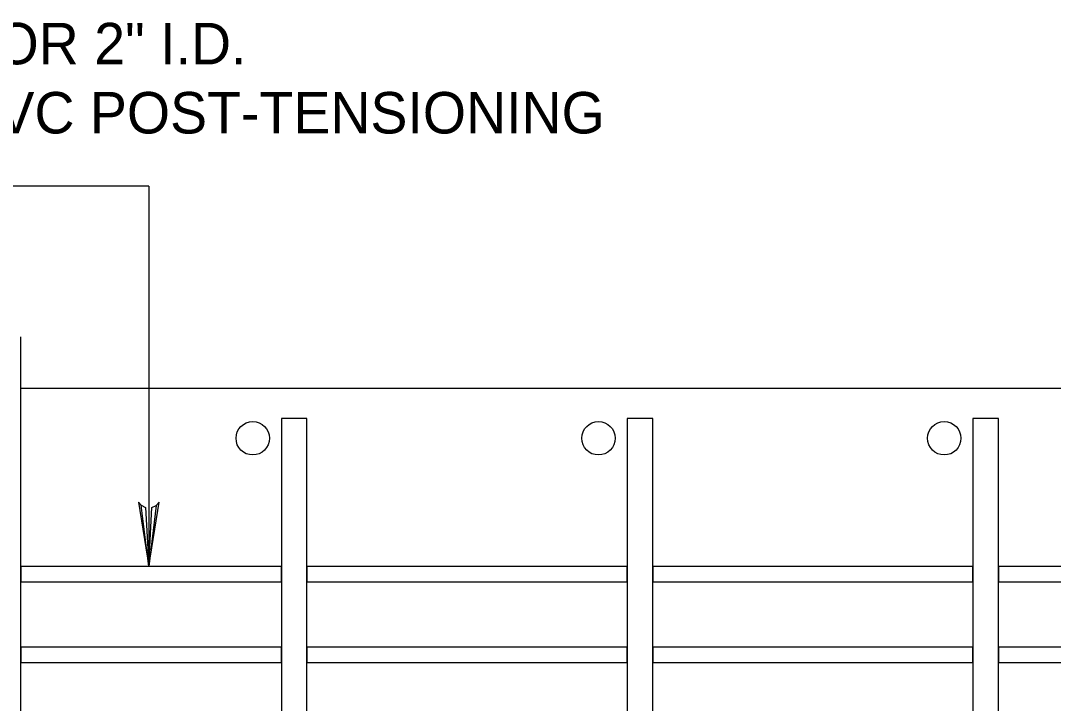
# Model space of a CAD drawing. Extents: x 641328 to 643024, y 298283 to 300065.
# Drawn here: x 642584.3 to 642658.9, y 299717.9 to 299767.3 of the extents above; entities that cross this region are included whole.
import ezdxf

# ---------------------------------------------------------------- set-up
doc = ezdxf.new("R2010")
doc.units = 0
doc.layers.add('2', color=7, linetype='Continuous')
doc.layers.add('63', color=7, linetype='Continuous')

msp = doc.modelspace()

# ---------------------------------------------------------------- linework, layer by layer
at = {"layer": '2'}
for p, q in [((642593.54, 299755.271), (642576.092, 299755.271)), ((642584.298, 299686.504), (642584.298, 299744.382)), ((642687.271, 299740.639), (642584.298, 299740.639)), ((642604.973, 299738.468), (642603.123, 299738.468)), ((642603.123, 299738.468), (642603.123, 299680.655)), ((642604.973, 299680.655), (642604.973, 299738.468)), ((642629.973, 299738.468), (642628.123, 299738.468)), ((642628.123, 299738.468), (642628.123, 299680.655)), ((642629.973, 299680.655), (642629.973, 299738.468)), ((642654.973, 299738.468), (642653.123, 299738.468)), ((642653.123, 299738.468), (642653.123, 299680.655)), ((642654.973, 299680.655), (642654.973, 299738.468))]:
    msp.add_line(p, q, dxfattribs=at)
for points in [[(642603.123, 299727.775), (642584.298, 299727.775), (642584.298, 299726.664), (642603.123, 299726.664)], [(642628.123, 299727.775), (642604.973, 299727.775), (642604.973, 299726.664), (642628.123, 299726.664)], [(642653.123, 299727.775), (642629.973, 299727.775), (642629.973, 299726.664), (642653.123, 299726.664)], [(642674.273, 299727.775), (642654.973, 299727.775), (642654.973, 299726.664), (642674.273, 299726.664)], [(642603.123, 299721.94), (642584.298, 299721.94), (642584.298, 299720.829), (642603.123, 299720.829)], [(642628.123, 299721.94), (642604.973, 299721.94), (642604.973, 299720.829), (642628.123, 299720.829)], [(642653.123, 299721.94), (642629.973, 299721.94), (642629.973, 299720.829), (642653.123, 299720.829)], [(642674.273, 299721.94), (642654.973, 299721.94), (642654.973, 299720.829), (642674.273, 299720.829)]]:
    msp.add_lwpolyline(points, close=True, dxfattribs=at)
for centre in [(642601.052, 299737.047), (642626.052, 299737.047), (642651.052, 299737.047)]:
    msp.add_circle(centre, 1.207, dxfattribs=at)
at = {"layer": '63'}
msp.add_line((642593.54, 299755.271), (642593.54, 299727.775), dxfattribs=at)
msp.add_lwpolyline([(642592.984, 299732.204), (642593.305, 299732.039), (642593.54, 299727.775), (642592.984, 299732.204), (642592.79, 299732.431), (642593.54, 299727.775), (642593.751, 299732.036), (642594.068, 299732.191), (642593.54, 299727.775), (642594.28, 299732.431), (642594.068, 299732.191)], dxfattribs=at)

# ---------------------------------------------------------------- texts
at = {"layer": '2'}
for s, p in [('1 1/2" I.D. OR 2" I.D.', (642563.642, 299764.095)), ('SCH. 40 PVC POST-TENSIONING', (642563.642, 299759.095))]:
    msp.add_text(s, height=2.99999, dxfattribs=at).set_placement(p)

doc.saveas('drawing.dxf')
